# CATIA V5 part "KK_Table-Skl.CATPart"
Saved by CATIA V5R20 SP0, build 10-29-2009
Part number: Table-Skl
Publications: "Point.3", "Point.4", "Point.5", "Point.6", "Point.7", "Point.8"
Bounding box of the stored display mesh (mm): x -63.303 to 63.395, y -48.269 to 61.671, z 100 to 100
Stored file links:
  G:\Khaled_CFAO_2011\ST2M\ST2M_GR1\msallin\Khaled\Version_Finale\KK_Table-Skl.CATPart
  C:\Users\Mathieu\Desktop\Think Motion\JOUG-MELEE2.CATProduct
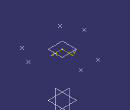
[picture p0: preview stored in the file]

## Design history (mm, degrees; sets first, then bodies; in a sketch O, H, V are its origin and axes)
External parameters (linked from other documents)
  `External.Taille du joug` = 100 mm
Set1
  Line1 to Line3: linked copy from another document
  Point1: linked copy from another document
  Point2: linked copy from another document
Set2
  Plane1: type Offset, RefPlane xy-plane, Offset 100 {= `External.Taille du joug`}
  Point3: (0, 0, 0), relative to Sketch1.P1
  Point4: (0, 0, 0), relative to Sketch1.P2
  Point5: (0, 0, 0), relative to Sketch1.P3
  Point6: (0, 0, 0), relative to Sketch1.P4
  Point7: (0, 0, 0), relative to Sketch1.P5
  Point8: (0, 0, 0), relative to Sketch1.P6
Body1 (main body)
  Sketch1 on Plane1, origin (0, 0, 100), H (1, 0, 0), V (0, 1, 0)
    point P1 (-19.9998, 61.5349)
    point P2 (20, 61.6709)
    point P3 (63.3948, -13.2654)
    point P4 (43.5126, -47.9742)
    point P5 (-43.1856, -48.2688)
    point P6 (-63.3032, -13.696)
    construction line L1 (175.9863, -43.1876) -> (99.9994, 0.3398)
    point P7 (99.9994, 0.3398)
    reference projected line E1 (-50.294, 86.4321) -> (49.7054, 86.7719) from Line1
    reference projected line E2 (-50.294, 86.4321) -> (49.7054, 86.7719) from Line1
    reference projected line E3 (99.9994, 0.3398) -> (50.294, -86.4321) from Line2
    reference projected line E4 (99.9994, 0.3398) -> (50.294, -86.4321) from Line2
    reference projected line E5 (-49.7054, -86.7719) -> (-99.9994, -0.3398) from Line3
    reference projected line E6 (-49.7054, -86.7719) -> (-99.9994, -0.3398) from Line3
    reference projected point E7 (99.9994, 0.3398) from Point1
    reference projected line E8 (99.9994, 0.3398) -> (50.294, -86.4321) from Line2
    axis line L2 (-108.7528, -121.131) -> (-49.7054, -86.7719)
    point P10 (-49.7054, -86.7719)
    reference projected point E9 (-49.7054, -86.7719) from Point2
    reference projected line E10 (-49.7054, -86.7719) -> (-99.9994, -0.3398) from Line3
    distance P1 E1 = 25 {= `External.Taille du joug` /4}
    distance P2 E2 = 25 {= `External.Taille du joug` /4}
    distance P2 P1 = 40 {= `External.Taille du joug` *2/5}
    distance P2 V = 20 {= Sketch1.distance(P2 P1) /2}
    distance P3 E3 = 25 {= `External.Taille du joug` /4}
    distance P4 E4 = 25 {= `External.Taille du joug` /4}
    distance P5 E5 = 25 {= `External.Taille du joug` /4}
    distance P6 E6 = 25 {= `External.Taille du joug` /4}
    distance P4 P3 = 40 {= `External.Taille du joug` *2/5}
    distance P5 P6 = 40 {= `External.Taille du joug` *2/5}
    angle E8 L1 = 90
    distance L1 P3 = 30 {= `External.Taille du joug` *3/10}
    angle L2 E10 = 90
    distance L2 P5 = 30 {= `External.Taille du joug` *3/10}
    coincidence: E7 P7, E9 P10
